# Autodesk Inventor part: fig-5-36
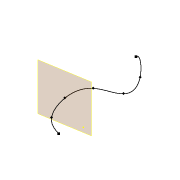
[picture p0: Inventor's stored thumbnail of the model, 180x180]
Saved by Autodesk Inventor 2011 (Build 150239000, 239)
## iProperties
Created: 2010-02
Part Number: fig-5-36
Document SubType Name: Modeling
Designer: CADSoft
Density: 1 g/cm^3
Author: CADSoft
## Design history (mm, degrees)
sketch "Sketch1"
  geometry: 8 further points
  constraints: 8 other
workplane "Work Plane1"
workplane "Work Plane2"
